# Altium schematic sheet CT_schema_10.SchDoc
size 741 x 377 mm
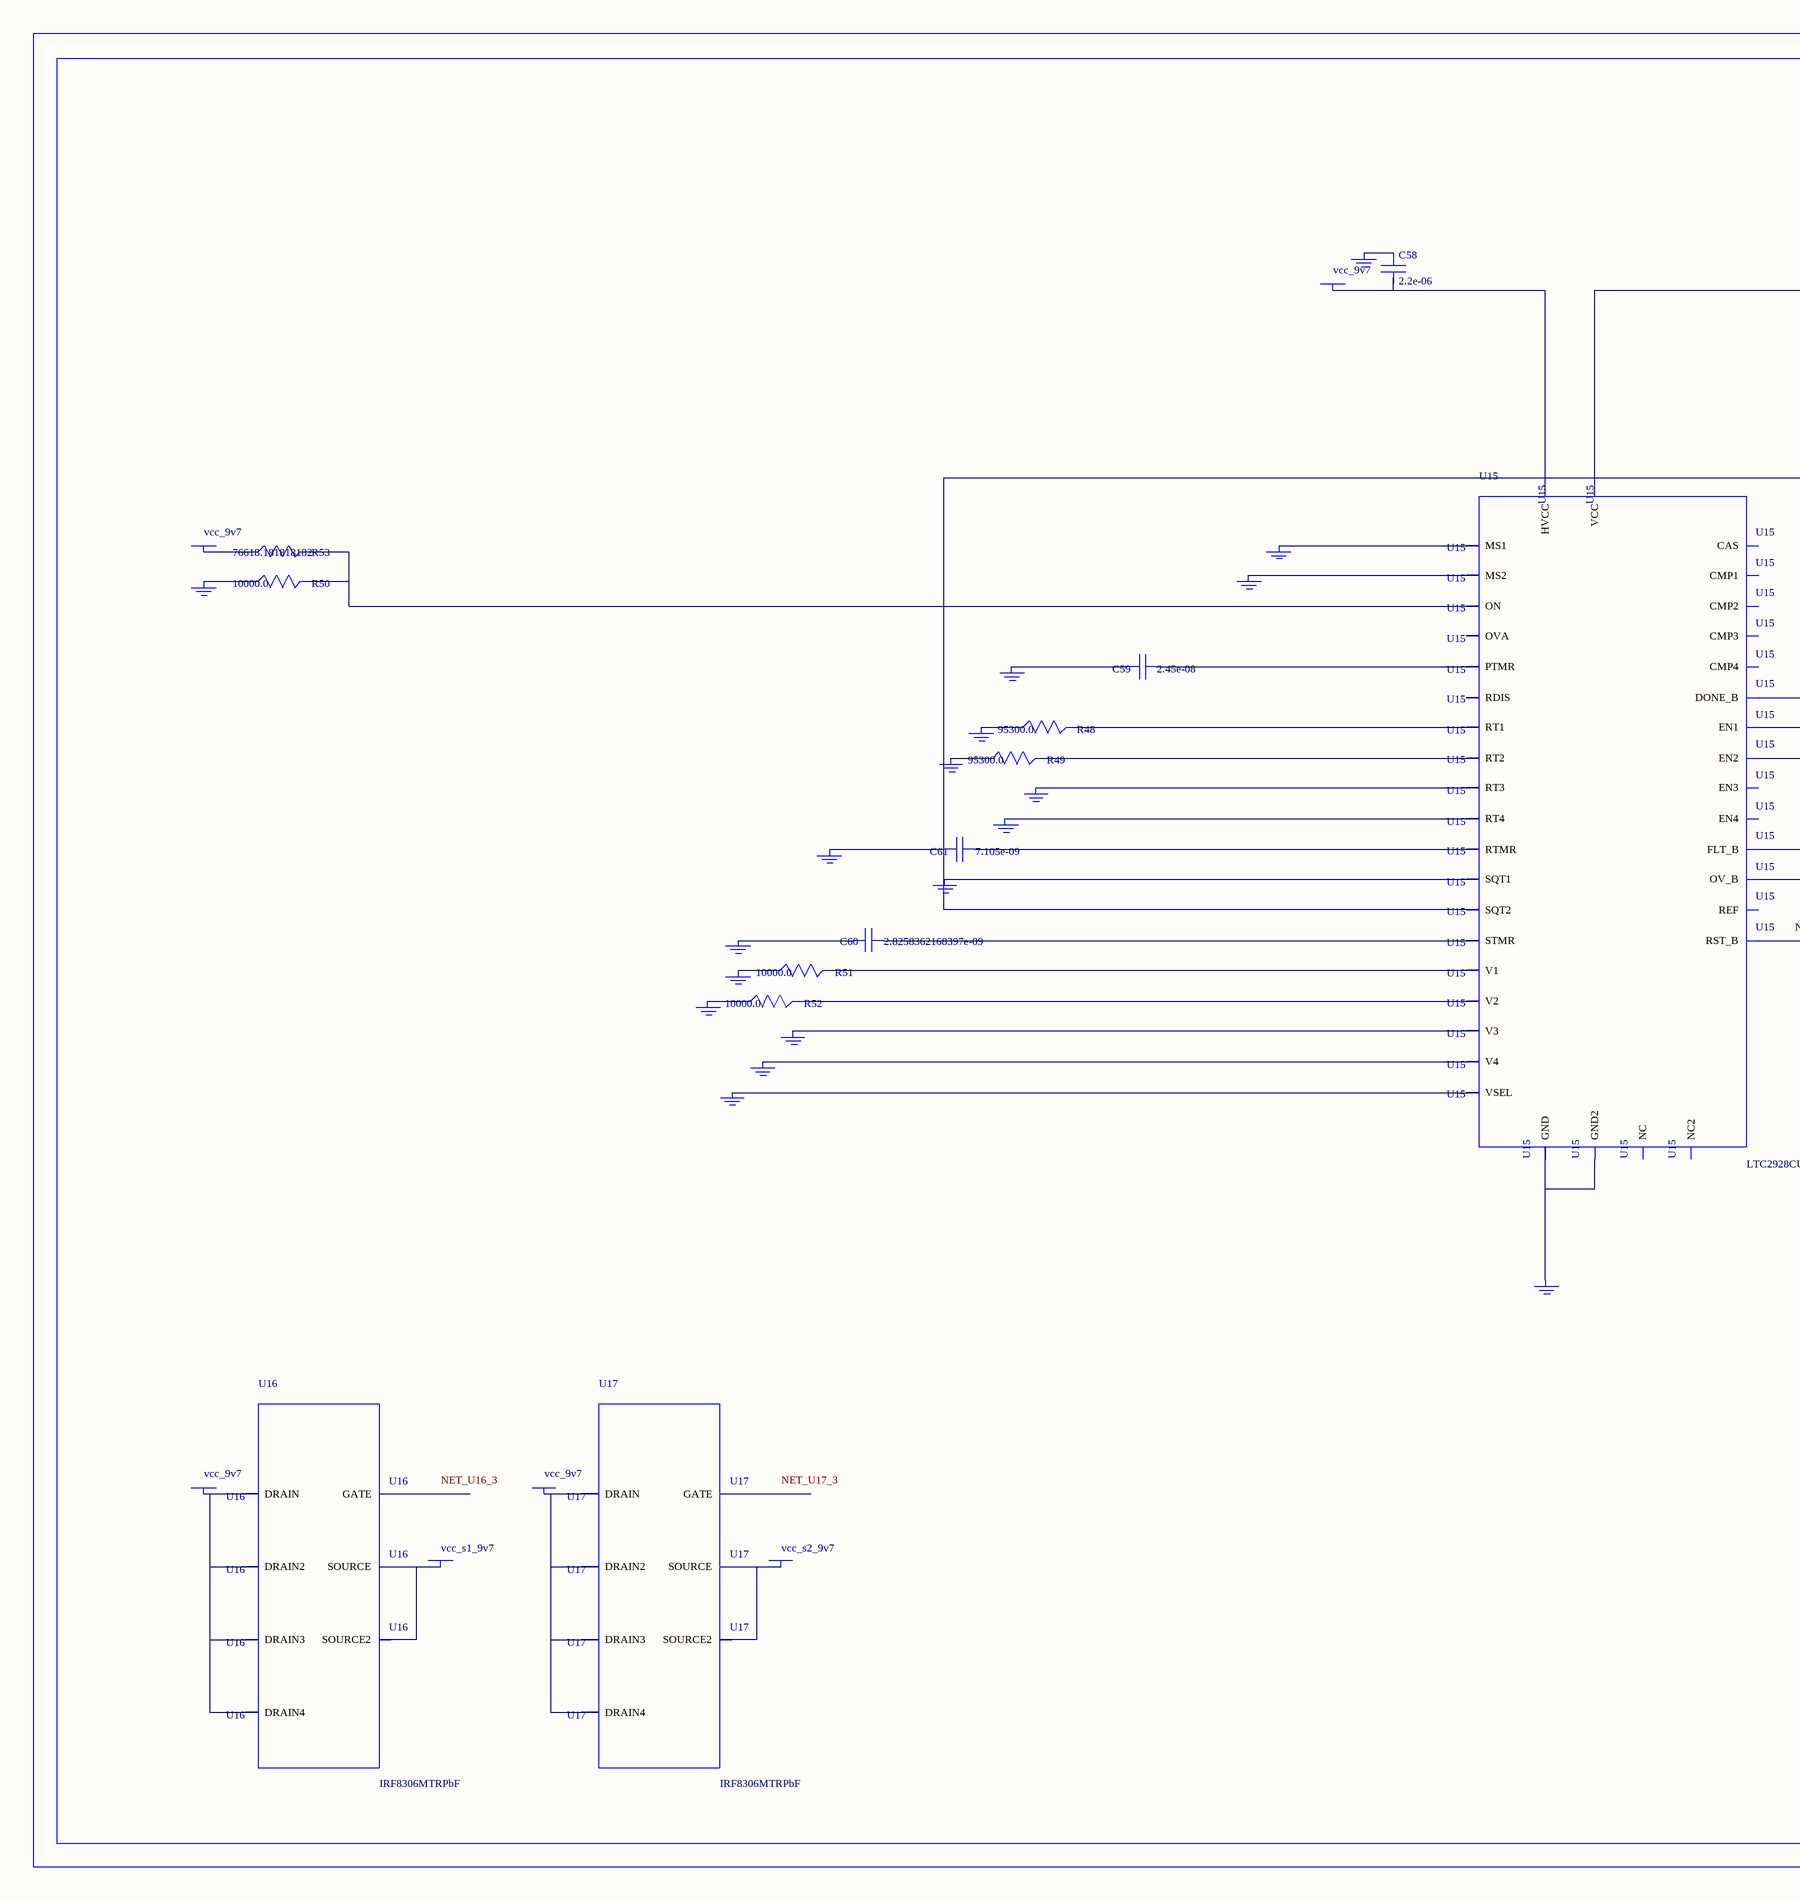
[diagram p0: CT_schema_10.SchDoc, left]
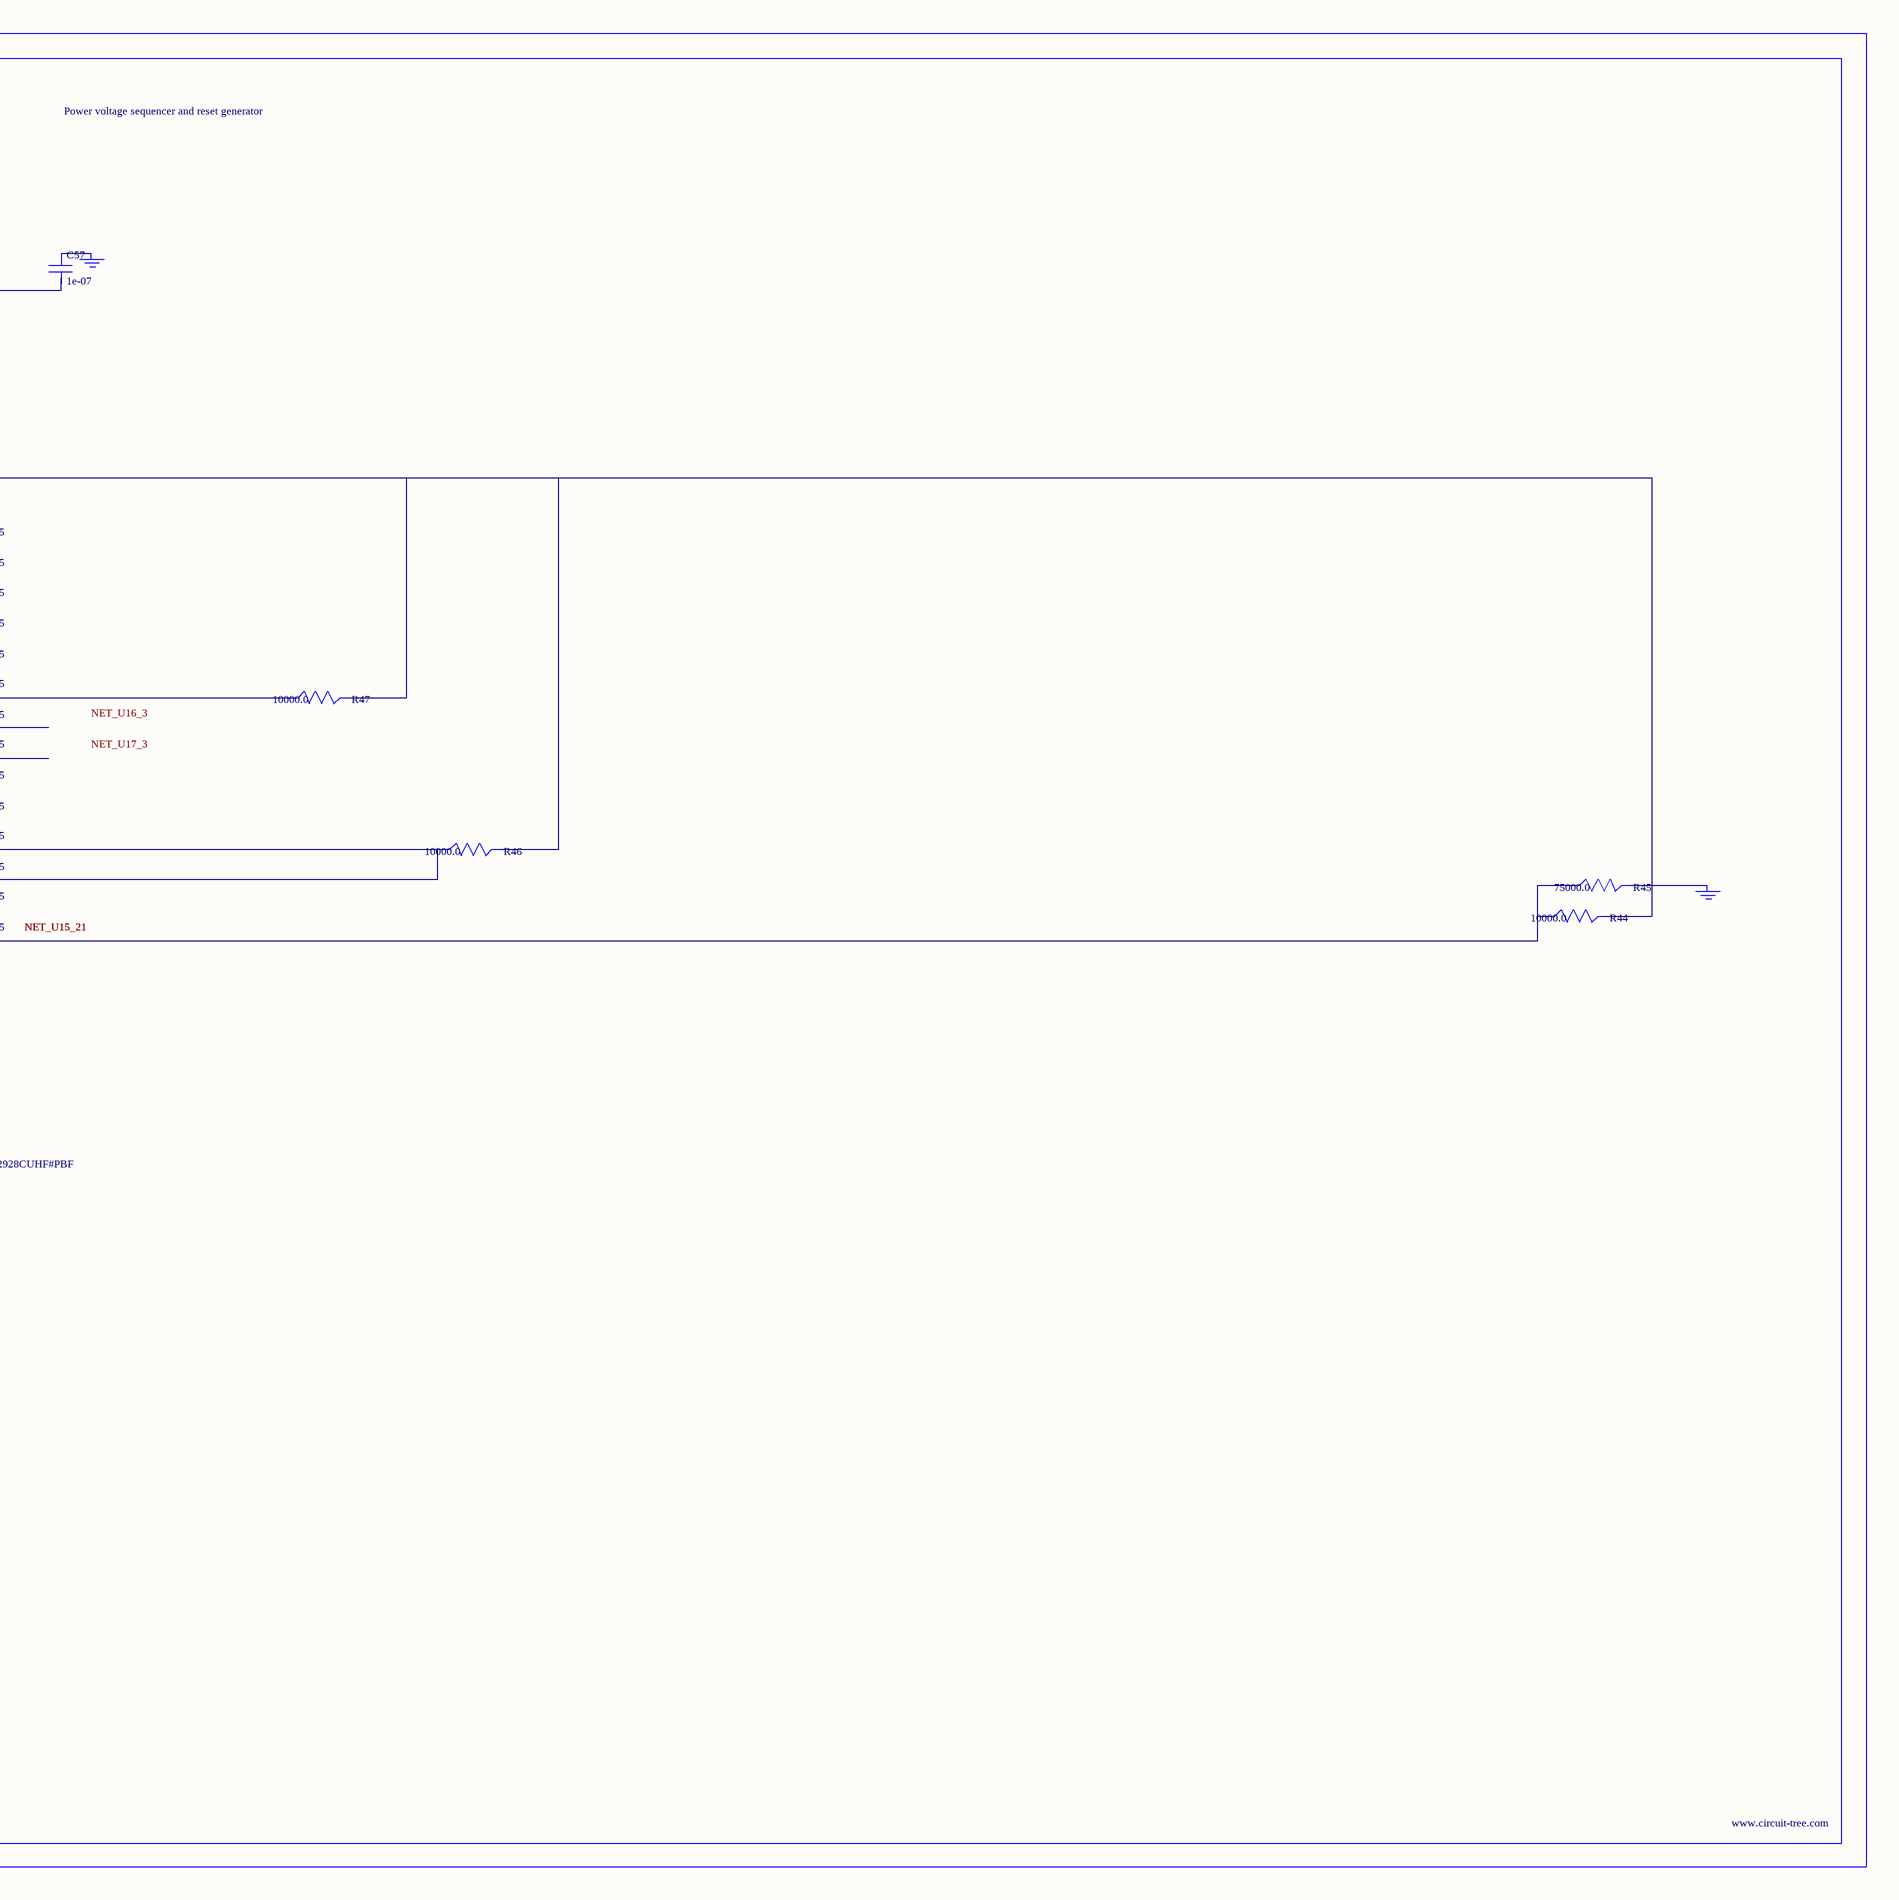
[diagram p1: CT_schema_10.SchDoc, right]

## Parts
BORDER9  (no value)
C57  1e-07  [C0402]
C58  2.2e-06  [C0603]
C59  2.45e-08  [R0603]
C60  2.8258362168397e-09  [R0603]
C61  7.105e-09  [R0603]
GND_INSTANCE_9_0  (no value)
GND_INSTANCE_9_1  (no value)
GND_INSTANCE_9_2  (no value)
GND_INSTANCE_9_3  (no value)
GND_INSTANCE_9_4  (no value)
GND_INSTANCE_9_5  (no value)
GND_INSTANCE_9_6  (no value)
GND_INSTANCE_9_7  (no value)
GND_INSTANCE_9_8  (no value)
GND_INSTANCE_9_9  (no value)
GND_INSTANCE_9_10  (no value)
GND_INSTANCE_9_11  (no value)
GND_INSTANCE_9_12  (no value)
GND_INSTANCE_9_13  (no value)
GND_INSTANCE_9_14  (no value)
GND_INSTANCE_9_15  (no value)
GND_INSTANCE_9_16  (no value)
GND_INSTANCE_9_17  (no value)
GND_INSTANCE_9_18  (no value)
GND_INSTANCE_9_19  (no value)
POWER_INSTANCE_9_0  vcc_9v7
POWER_INSTANCE_9_1  vcc_9v7
POWER_INSTANCE_9_2  vcc_9v7
POWER_INSTANCE_9_3  vcc_s1_9v7
POWER_INSTANCE_9_4  vcc_9v7
POWER_INSTANCE_9_5  vcc_s2_9v7
R44  10000.0  [R0603]
R45  75000.0  [R0603]
R46  10000.0  [R0603]
R47  10000.0  [R0603]
R48  95300.0  [R0603]
R49  95300.0  [R0603]
R50  10000.0  [R0603]
R51  10000.0  [R0603]
R52  10000.0  [R0603]
R53  76618.181818182  [R0603]
U15  LTC2928CUHF#PBF  [QFN-38_UHF]
U16  IRF8306MTRPbF  [IRF8306MTRPBF]
U17  IRF8306MTRPbF  [IRF8306MTRPBF]

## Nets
NetC57_1: C57.1 GND_INSTANCE_9_10.0(GND)
NetC57_2: C57.2 C61.2 GND_INSTANCE_9_5.0(GND) GND_INSTANCE_9_15.0(GND) R44.2 R46.2 R47.2 U15.10(SQT1) U15.11(SQT2) U15.22(VCC)
NetC58_1: C58.1 GND_INSTANCE_9_11.0(GND)
NetC58_2: C58.2 POWER_INSTANCE_9_1.0(PWR) U15.23(HVCC)
NetC59_1: C59.1 U15.27(PTMR)
NetC59_2: C59.2 GND_INSTANCE_9_14.0(GND)
NetC60_1: C60.1 U15.26(STMR)
NetC60_2: C60.2 GND_INSTANCE_9_13.0(GND)
NetC61_1: C61.1 U15.28(RTMR)
NetGND_INSTANCE_9_0_0: GND_INSTANCE_9_0.0(GND) R51.1
NetGND_INSTANCE_9_1_0: GND_INSTANCE_9_1.0(GND) R48.1
NetGND_INSTANCE_9_2_0: GND_INSTANCE_9_2.0(GND) R49.1
NetGND_INSTANCE_9_3_0: GND_INSTANCE_9_3.0(GND) U15.8(RT3)
NetGND_INSTANCE_9_4_0: GND_INSTANCE_9_4.0(GND) U15.9(RT4)
NetGND_INSTANCE_9_6_0: GND_INSTANCE_9_6.0(GND) U15.12(MS1)
NetGND_INSTANCE_9_7_0: GND_INSTANCE_9_7.0(GND) U15.13(MS2)
NetGND_INSTANCE_9_8_0: GND_INSTANCE_9_8.0(GND) R50.1
NetGND_INSTANCE_9_9_0: GND_INSTANCE_9_9.0(GND) R45.2
NetGND_INSTANCE_9_12_0: GND_INSTANCE_9_12.0(GND) U15.25(VSEL)
NetGND_INSTANCE_9_16_0: GND_INSTANCE_9_16.0(GND) U15.30(V4)
NetGND_INSTANCE_9_17_0: GND_INSTANCE_9_17.0(GND) U15.32(V3)
NetGND_INSTANCE_9_18_0: GND_INSTANCE_9_18.0(GND) R52.1
NetGND_INSTANCE_9_19_0: GND_INSTANCE_9_19.0(GND) U15.24(GND) U15.39(GND2)
NetPOWER_INSTANCE_9_0_0: POWER_INSTANCE_9_0.0(PWR) R53.1
NetPOWER_INSTANCE_9_2_0: POWER_INSTANCE_9_2.0(PWR) U16.1(DRAIN) U16.2(DRAIN2) U16.6(DRAIN3) U16.7(DRAIN4)
NetPOWER_INSTANCE_9_3_0: POWER_INSTANCE_9_3.0(PWR) U16.4(SOURCE) U16.5(SOURCE2)
NetPOWER_INSTANCE_9_4_0: POWER_INSTANCE_9_4.0(PWR) U17.1(DRAIN) U17.2(DRAIN2) U17.6(DRAIN3) U17.7(DRAIN4)
NetPOWER_INSTANCE_9_5_0: POWER_INSTANCE_9_5.0(PWR) U17.4(SOURCE) U17.5(SOURCE2)
NetR44_1: R44.1 R45.1 U15.21(RST_B)
NetR46_1: R46.1 U15.19(FLT_B) U15.20(OV_B)
NetR47_1: R47.1 U15.18(DONE_B)
NetR48_2: R48.2 U15.6(RT1)
NetR49_2: R49.2 U15.7(RT2)
NetR50_2: R50.2 R53.2 U15.16(ON)
NetR51_2: R51.2 U15.3(V1)
NetR52_2: R52.2 U15.38(V2)

Not connected (* = marked no-connect by the designer): U15 1(OVA) 2(EN1) 4(NC) 5(REF) 14(RDIS) 15(CAS) 17(NC2) 29(EN4) 31(EN3) 33(CMP3) 34(CMP4) 35(CMP1) 36(CMP2) 37(EN2); U16 3(GATE); U17 3(GATE)

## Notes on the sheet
- Labels drawn without touching a wire or pin: NET_U16_3, NET_U17_3

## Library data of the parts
BORDER9 = BORDER_PAGE9
C57 = C0402C104K3RACTU
C58 = GRM188R61H225KE1115D
C59 = C59
C60 = C60
C61 = C61
GND_INSTANCE_9_0-GND_INSTANCE_9_19 = GND
POWER_INSTANCE_9_0-POWER_INSTANCE_9_5 = PWR
R44 R46 R47 R50-R52 = RC0603JR-0710KL
R45 = RC0603JR-0775KL
R48 R49 = RC0603FR-0795K3L
R53 = R53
